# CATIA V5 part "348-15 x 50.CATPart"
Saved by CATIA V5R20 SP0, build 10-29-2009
Part number: 348-15 x 50
Definition: NONE
Nomenclature: 348-15 x 50
Source: Unknown
Description: 348-15 x 50
Bounding box of the stored display mesh (mm): x 0 to 50, y -13 to 13, z -13 to 13
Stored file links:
  C:\Users\Utente\Desktop\IO LAVORO\3D X SITO CF\X SITO\3D files 348\348-15 x 50.CATPart
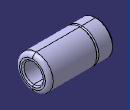
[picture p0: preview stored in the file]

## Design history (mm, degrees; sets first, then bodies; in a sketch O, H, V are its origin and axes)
Body1 "348-15 x 50" (main body)
  Solid1: solid without history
